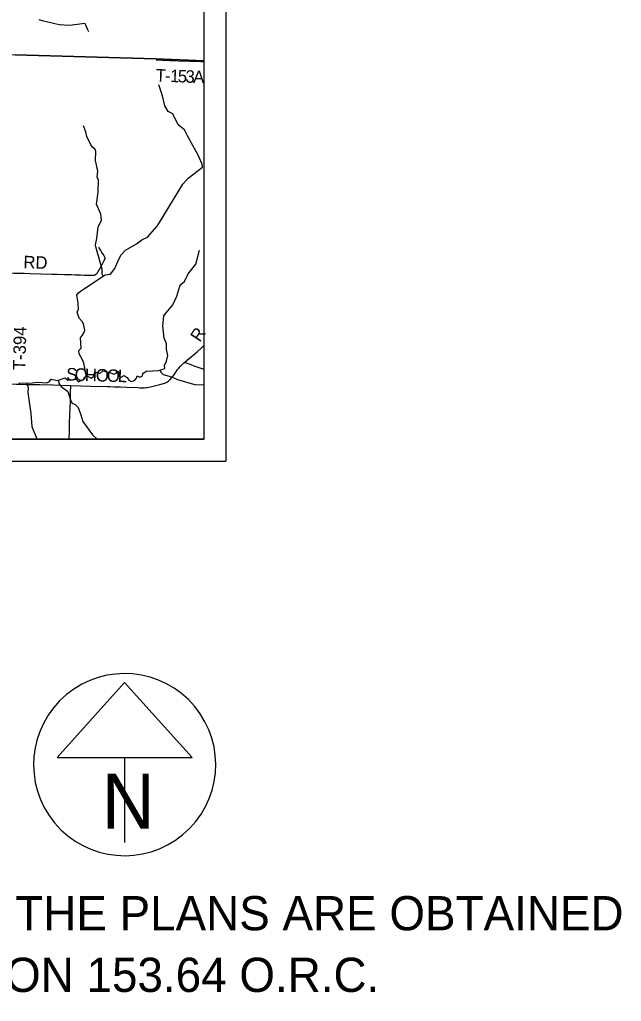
# Model space of a CAD drawing. Extents: x 0 to 34, y 0 to 22.
# Drawn here: x 8.561 to 11.301, y 11.839 to 16.31 of the extents above; entities that cross this region are included whole.
import ezdxf

# ---------------------------------------------------------------- set-up
doc = ezdxf.new("R2010")
doc.units = 0
for name, color, linetype in [('GM_X_County', 7, 'Continuous'), ('GM_X_County_Road', 7, 'Continuous'), ('GM_X_County_Road_Text', 7, 'Continuous'), ('GM_X_Minor_River', 7, 'Continuous'), ('GM_X_Township', 7, 'Continuous'), ('GM_X_Township_Road', 7, 'Continuous'), ('GM_X_Township_Road_Text', 7, 'Continuous'), ('SH_Data', 7, 'Continuous'), ('SH_Text', 7, 'Continuous')]:
    doc.layers.add(name, color=color, linetype=linetype)

msp = doc.modelspace()

# ---------------------------------------------------------------- linework, layer by layer
at = {"layer": 'GM_X_County'}
msp.add_lwpolyline([(7.0736, 21.2003), (2.6013, 21.2003), (2.6013, 14.4003), (9.4013, 14.4003), (9.4013, 21.1598)], dxfattribs=at)
at = {"layer": 'GM_X_County_Road'}
for points in [[(9.3117, 14.7488), (9.324, 14.7593), (9.3691, 14.7973), (9.388, 14.8135), (9.396, 14.8207), (9.4013, 14.8258)], [(8.7936, 14.6437), (8.8853, 14.6409), (8.9606, 14.6389), (8.9723, 14.6387), (8.9935, 14.6383), (9.0183, 14.6373), (9.0493, 14.6361), (9.099, 14.634), (9.109, 14.6337), (9.1202, 14.6335), (9.1302, 14.6336), (9.1372, 14.6341), (9.1421, 14.6346), (9.1483, 14.6355), (9.1574, 14.6373), (9.1999, 14.6478), (9.2169, 14.6525), (9.222, 14.6543), (9.2255, 14.6556), (9.2289, 14.6571), (9.2328, 14.6593), (9.2347, 14.6606), (9.2382, 14.6632), (9.2422, 14.6667), (9.2446, 14.6689), (9.2548, 14.6807), (9.2588, 14.6854), (9.2632, 14.6912), (9.2749, 14.7083), (9.2804, 14.716), (9.2861, 14.7231), (9.2942, 14.7323), (9.2999, 14.7382), (9.3075, 14.7452), (9.3117, 14.7488)], [(8.4852, 14.6492), (8.4893, 14.65), (8.4932, 14.6505), (8.4957, 14.6508), (8.4983, 14.651), (8.5014, 14.6512), (8.5052, 14.6512), (8.5107, 14.6512), (8.5184, 14.6511), (8.5449, 14.65), (8.5614, 14.6496), (8.5908, 14.6489), (8.6536, 14.6478), (8.7115, 14.6461), (8.7434, 14.645), (8.7936, 14.6437)]]:
    msp.add_lwpolyline(points, dxfattribs=at)
at = {"layer": 'GM_X_Minor_River'}
for points in [[(8.6481, 16.3111), (8.6629, 16.3058), (8.7418, 16.288), (8.7881, 16.2844), (8.8582, 16.2938), (8.8693, 16.2684), (8.8739, 16.2567)], [(8.8626, 14.6858), (8.8658, 14.6835), (8.8538, 14.7449), (8.848, 14.7608), (8.8316, 14.7885), (8.8312, 14.8036), (8.8417, 14.8136), (8.8381, 14.8602), (8.8471, 14.8732), (8.855, 14.8861), (8.8572, 14.896), (8.8526, 14.924), (8.8464, 14.9358), (8.8323, 14.9505), (8.8235, 14.9785), (8.8287, 14.9918), (8.8278, 15.0184), (8.8216, 15.0559), (8.8284, 15.0662), (8.8382, 15.0727), (8.9409, 15.1419), (8.9512, 15.1476), (8.9743, 15.1515), (8.995, 15.1762), (9.0077, 15.2086), (9.022, 15.2371), (9.0431, 15.2603), (9.0934, 15.2894), (9.1168, 15.3069), (9.144, 15.32), (9.1874, 15.3691), (9.1975, 15.3858), (9.3047, 15.5609), (9.3292, 15.5883), (9.3945, 15.6379), (9.3922, 15.6523), (9.3746, 15.6925), (9.3249, 15.7814), (9.3115, 15.8075), (9.2837, 15.8313), (9.2585, 15.8813), (9.2379, 15.8922), (9.2227, 15.9175), (9.2118, 15.9634), (9.1942, 16.0126)], [(8.9419, 15.1424), (8.9375, 15.1513), (8.9362, 15.1733), (8.9077, 15.2749), (8.9065, 15.2851), (8.9132, 15.3129), (8.9194, 15.3656), (8.934, 15.3961), (8.9309, 15.4237), (8.9113, 15.4699), (8.9187, 15.5246), (8.9199, 15.5796), (8.9138, 15.5929), (8.9171, 15.6206), (8.9062, 15.668), (8.9083, 15.709), (8.9048, 15.7192), (8.8927, 15.7294), (8.885, 15.7392), (8.867, 15.7786), (8.8628, 15.7995), (8.8513, 15.8267)], [(8.5575, 14.654), (8.6185, 14.6566), (8.6454, 14.6586), (8.6856, 14.6554), (8.6969, 14.6615), (8.7048, 14.6733), (8.7337, 14.667), (8.7685, 14.6789), (8.7806, 14.6687), (8.817, 14.6727), (8.8292, 14.6609), (8.8515, 14.6717), (8.8568, 14.6823), (8.867, 14.6884), (8.8871, 14.6775), (8.8973, 14.6852), (8.9003, 14.6966), (8.9146, 14.7038), (8.9268, 14.6989), (8.9404, 14.71), (8.9723, 14.7033), (8.9901, 14.6954), (9.0015, 14.7), (9.0014, 14.7099), (9.012, 14.7065), (9.0129, 14.6864), (9.0232, 14.6815), (9.0364, 14.6896), (9.0501, 14.6805), (9.0588, 14.6677), (9.0687, 14.6624), (9.0835, 14.667), (9.0933, 14.6773), (9.0967, 14.6879), (9.1084, 14.6823), (9.1205, 14.6884), (9.1224, 14.6991), (9.1375, 14.709), (9.1951, 14.7123), (9.2216, 14.7215), (9.2211, 14.7344), (9.2301, 14.7553), (9.2357, 14.78), (9.2295, 14.8096), (9.2305, 14.8331), (9.2194, 14.86), (9.213, 14.9161), (9.2181, 14.9606), (9.2279, 14.9746), (9.2581, 15.0112), (9.2764, 15.05), (9.291, 15.0956), (9.2981, 15.1074), (9.3114, 15.1173), (9.3279, 15.1519), (9.3629, 15.1969), (9.38, 15.2599)], [(9.2008, 14.7143), (9.2038, 14.7051), (9.2149, 14.6945), (9.2521, 14.6837), (9.2802, 14.6705), (9.3633, 14.647), (9.4013, 14.6488)], [(8.7368, 14.6681), (8.7417, 14.6514), (8.7501, 14.639), (8.7801, 14.6163), (8.7936, 14.5739), (8.8001, 14.5637), (8.8138, 14.5573), (8.8275, 14.5429), (8.8398, 14.5107), (8.8494, 14.4793), (8.8929, 14.4195), (8.9133, 14.4003)], [(8.5937, 14.6556), (8.5993, 14.6353), (8.5978, 14.6125), (8.6116, 14.5162), (8.6164, 14.457), (8.6394, 14.4003)]]:
    msp.add_lwpolyline(points, dxfattribs=at)
at = {"layer": 'GM_X_Township'}
msp.add_line((9.4013, 16.1226), (9.4013, 21.1598), dxfattribs=at)
for points in [[(6.2234, 21.2003), (6.1733, 19.6859), (6.1731, 19.6818), (6.1731, 19.6616), (6.1717, 19.6397), (6.1473, 18.845), (6.11, 17.7459), (6.0911, 17.2548), (6.0778, 16.7443), (6.0664, 16.4042), (6.0598, 16.2379), (6.2085, 16.2337), (6.3056, 16.228), (6.5048, 16.2253), (7.5772, 16.1862), (7.7357, 16.1804), (8.4842, 16.1527), (8.5405, 16.1503), (9.1818, 16.131), (9.4013, 16.1226)], [(9.4013, 16.1226), (9.1818, 16.131), (8.5405, 16.1503)], [(6.0009, 14.4003), (9.4013, 14.4003), (9.4013, 16.1226)]]:
    msp.add_lwpolyline(points, dxfattribs=at)
at = {"layer": 'GM_X_Township_Road'}
for points in [[(9.1825, 16.127), (9.2119, 16.1255), (9.244, 16.1242), (9.2626, 16.1236), (9.2829, 16.1232), (9.3398, 16.1213), (9.3669, 16.1204), (9.3859, 16.1196), (9.398, 16.1192), (9.4013, 16.1191)], [(8.6578, 15.1529), (8.708, 15.1513), (8.7321, 15.1507), (8.7656, 15.15), (8.7751, 15.1498), (8.7967, 15.1491), (8.8132, 15.1485), (8.8265, 15.1478), (8.8384, 15.1474), (8.8544, 15.1466), (8.8653, 15.1464), (8.8824, 15.1457), (8.8872, 15.1456), (8.892, 15.1456), (8.8936, 15.1456), (8.8951, 15.1457), (8.8965, 15.1459), (8.8976, 15.146), (8.8994, 15.1463), (8.9013, 15.1468), (8.9027, 15.1472), (8.9039, 15.1477), (8.9053, 15.1484), (8.9065, 15.149), (8.9079, 15.1499), (8.9092, 15.1509), (8.9101, 15.1517), (8.9112, 15.1526), (8.9129, 15.1544), (8.914, 15.1557), (8.9149, 15.1568), (8.916, 15.1584), (8.9168, 15.1596), (8.9189, 15.1631), (8.9214, 15.1675), (8.9332, 15.189), (8.9401, 15.2013), (8.9465, 15.213), (8.9485, 15.2172), (8.9494, 15.2194), (8.9497, 15.2202), (8.9499, 15.2208), (8.95, 15.2214), (8.9501, 15.2221), (8.9501, 15.2226), (8.9502, 15.2232), (8.9501, 15.2238), (8.95, 15.2248), (8.9499, 15.2256), (8.9497, 15.2264), (8.9493, 15.2276), (8.9489, 15.2285), (8.9484, 15.2297), (8.9472, 15.2316), (8.9407, 15.2416), (8.9359, 15.2491), (8.9338, 15.2526), (8.9303, 15.259), (8.9268, 15.2658), (8.9239, 15.2713), (8.9221, 15.2745)], [(8.5031, 15.157), (8.5168, 15.1566), (8.5342, 15.1561), (8.5492, 15.1559), (8.563, 15.1556), (8.5812, 15.1549), (8.6087, 15.1538), (8.6578, 15.1529)], [(9.4013, 14.7165), (9.3971, 14.7179), (9.3562, 14.7323), (9.3416, 14.7375), (9.3247, 14.744), (9.3117, 14.7488)], [(8.7861, 14.4003), (8.7861, 14.4008), (8.7875, 14.4346), (8.7888, 14.4696), (8.7901, 14.5119), (8.7912, 14.5397), (8.7922, 14.5709), (8.7929, 14.5934), (8.7932, 14.6117), (8.7936, 14.6437)]]:
    msp.add_lwpolyline(points, dxfattribs=at)
at = {"layer": 'SH_Data'}
for p, q in [((9.5, 21.2997), (9.5, 14.2997)), ((9.4, 21.1997), (9.4, 14.3997)), ((2.6, 14.3997), (9.4, 14.3997)), ((2.5, 14.2997), (9.5, 14.2997)), ((9.0392, 13.2905), (8.7317, 12.9493)), ((9.3468, 12.9493), (9.0392, 13.2905)), ((8.7317, 12.9493), (9.3468, 12.9493)), ((9.0392, 12.9493), (9.0392, 12.5625)), ((9.0392, 12.9168), (9.0392, 12.9168)), ((9.0392, 12.9168), (9.0392, 12.9168))]:
    msp.add_line(p, q, dxfattribs=at)
msp.add_arc((9.0393, 12.9168), 0.4148, 129.7798, 129.7633, dxfattribs=at)

# ---------------------------------------------------------------- texts
at = {"layer": 'GM_X_County_Road_Text'}
for s, rotation, p in [('R', 56.4831, (9.3813, 14.8382)), ('S', 358.1086, (8.7724, 14.6674)), ('C', 358.1111, (8.8108, 14.6661)), ('H', 358.1091, (8.8574, 14.6646)), ('O', 358.1103, (8.9074, 14.6629)), ('O', 358.1091, (8.9573, 14.6613)), ('L', 358.2556, (9.0075, 14.6596))]:
    msp.add_text(s, height=0.0568, rotation=rotation, dxfattribs=at).set_placement(p)
at = {"layer": 'GM_X_Township_Road_Text'}
for s, height, rotation, p in [('T', 0.0568, 357.7709, (9.1796, 16.0289)), ('1', 0.0568, 357.7722, (9.2454, 16.0263)), ('5', 0.0568, 357.7808, (9.2804, 16.025)), ('3', 0.0568, 357.7989, (9.3154, 16.0236)), ('A', 0.0568, 357.9902, (9.3506, 16.0223)), ('-', 0.0568, 357.7752, (9.2221, 16.0272)), ('RD', 0.05682, 358.0608, (8.5774, 15.1782)), ('T-394', 0.05682, 88.5955, (8.5871, 14.7133))]:
    msp.add_text(s, height=height, rotation=rotation, dxfattribs=at).set_placement(p)
at = {"layer": 'SH_Data'}
msp.add_text('N', height=0.25, rotation=360, dxfattribs=at).set_placement((8.9352, 12.6254))
at = {"layer": 'SH_Text'}
for s, p in [('THE LOCATION OF THE UNDERGROUND UTILITES SHOWN ON THE PLANS ARE OBTAINED', (2.1904, 12.1621)), ('FROM THE OWNER OF THE UTILITIES AS REQUIRED BY SECTION 153.64 O.R.C.', (2.1904, 11.8814))]:
    msp.add_text(s, height=0.155982, dxfattribs=at).set_placement(p)

doc.saveas('drawing.dxf')
